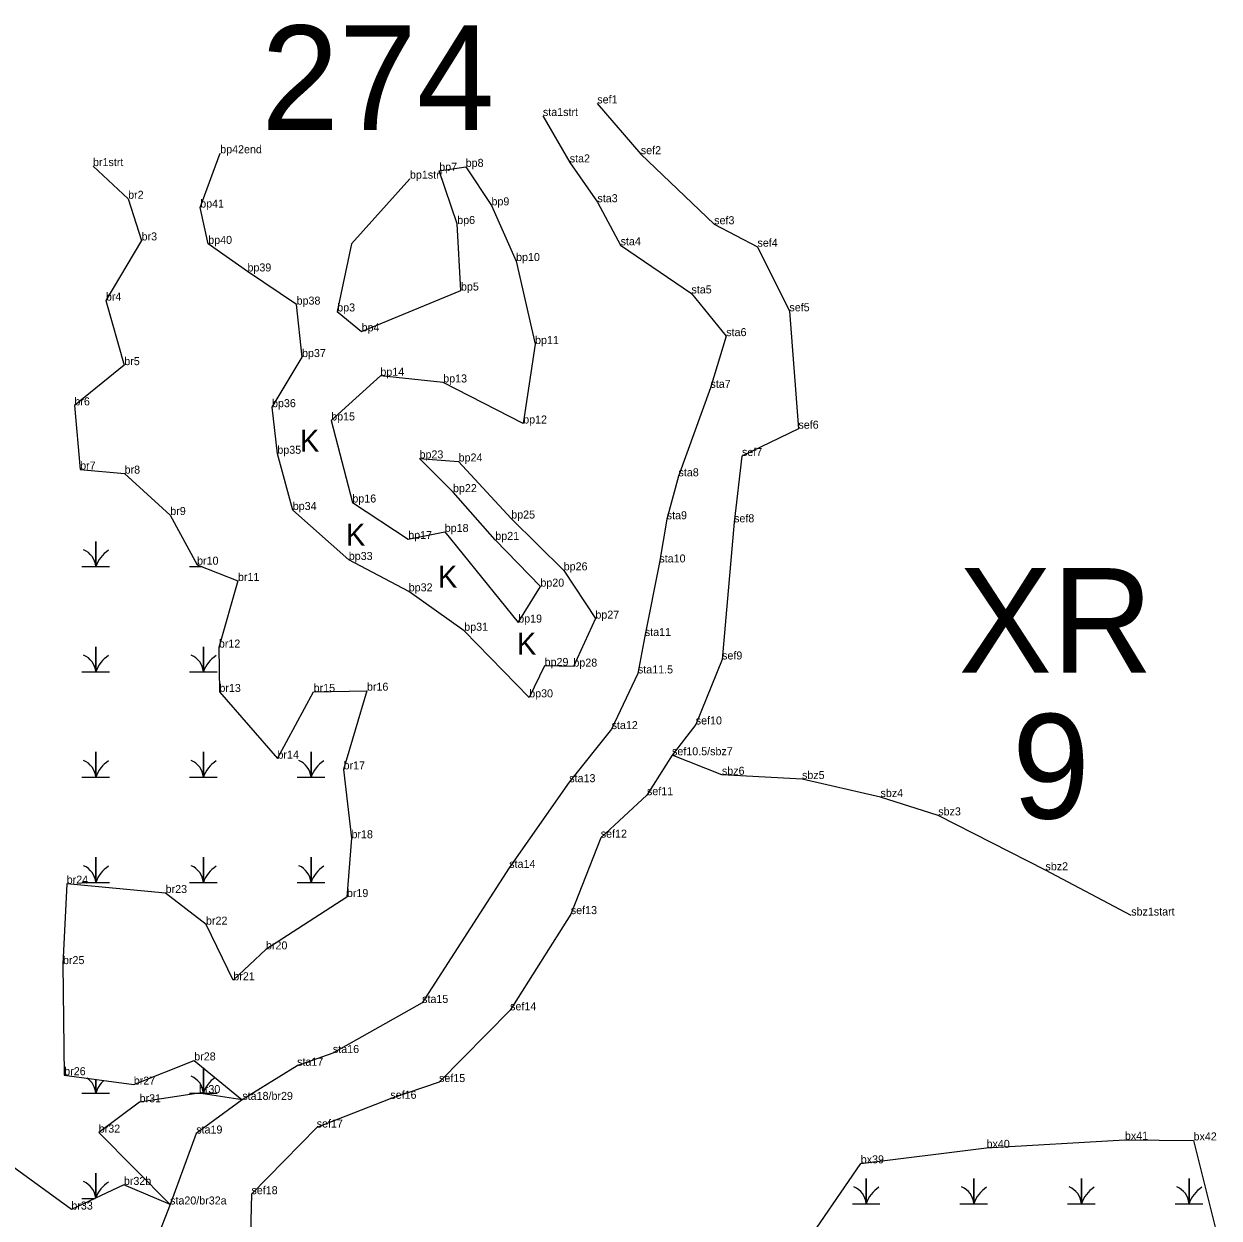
# Model space of a CAD drawing. Extents: x 2072529 to 2268796, y 436423 to 470397.
# Drawn here: x 2233128 to 2233875, y 438303 to 439049 of the extents above; entities that cross this region are included whole.
import ezdxf

# ---------------------------------------------------------------- set-up
doc = ezdxf.new("R2010")
doc.units = 0
for name, color, linetype in [('Default', 7, 'Continuous'), ('Exist Environmental Wetland Boundary', 7, 'Continuous'), ('Exist Environmental Wetland Boundary Cogo Comment', 7, 'Continuous'), ('Exist Environmental Wetland Boundary Cogo Point CELL', 7, 'Continuous'), ('Exist Hydro Jurisdictional Stream or Body of Water NEU Mitigable', 7, 'Continuous'), ('Exist Hydro Jurisdictional Stream or Body of Water NEU Mitigable Cogo Comment', 7, 'Continuous'), ('Exist Hydro Swamp or Marsh', 7, 'Continuous')]:
    doc.layers.add(name, color=color, linetype=linetype)

msp = doc.modelspace()

# ---------------------------------------------------------------- linework, layer by layer
at = {"layer": 'Exist Environmental Wetland Boundary'}
for points in [[(2233369.08, 438952.48), (2233332.65, 438911.67), (2233323.62, 438869.52), (2233338.88, 438857.06), (2233400.97, 438882.57), (2233398.61, 438924.17), (2233387.35, 438957.42), (2233403.91, 438959.87), (2233420.01, 438935.81), (2233435.4, 438901.03), (2233447.25, 438849.14), (2233439.82, 438799.48), (2233389.86, 438825.12), (2233350.61, 438829.32), (2233319.87, 438801.39), (2233333.11, 438750.11), (2233368, 438727.3), (2233390.81, 438731.69), (2233436.71, 438675.09), (2233450.58, 438697.52), (2233422.42, 438726.76), (2233395.99, 438756.59), (2233375.06, 438777.67), (2233399.5, 438775.74), (2233432.37, 438740.1), (2233465.14, 438707.71), (2233484.94, 438677.54), (2233471.2, 438647.57), (2233453.22, 438647.98), (2233443.58, 438628.34), (2233403.01, 438669.96), (2233368.31, 438694.6), (2233330.86, 438714.21), (2233295.86, 438745.43), (2233286.24, 438780.56), (2233282.91, 438809.69), (2233301.66, 438841), (2233298.26, 438873.8), (2233267.57, 438894.51), (2233243.05, 438911.72), (2233238.03, 438934.45), (2233250.54, 438968.37)], [(2233171.06, 438960.35), (2233193.01, 438939.93), (2233201.42, 438913.9), (2233179.1, 438876.33), (2233190.6, 438835.95), (2233159.43, 438810.81), (2233163.02, 438770.7), (2233190.8, 438768.17), (2233219.34, 438742.29), (2233236.09, 438711.26), (2233261.63, 438701.08), (2233249.69, 438659.45), (2233250.03, 438631.71), (2233286.3, 438590.05), (2233308.92, 438631.76), (2233342.21, 438632.51), (2233327.62, 438583.34), (2233332.55, 438540.3), (2233329.68, 438503.54), (2233279.12, 438470.84), (2233258.71, 438451.55), (2233241.66, 438486.32), (2233216.43, 438506.06), (2233154.63, 438511.91), (2233152.31, 438461.64), (2233153.08, 438392.21), (2233196.55, 438386.33), (2233234.31, 438401.46), (2233264.35, 438376.79), (2233237.2, 438381.03), (2233200.17, 438375.31), (2233174.65, 438356.35), (2233219.22, 438311.43), (2233190.35, 438323.66), (2233157.54, 438308.25), (2233110.77, 438342.31)], [(2233613.07, 438282.03), (2233650.73, 438337.13), (2233729.33, 438346.82), (2233815.78, 438351.89), (2233858.66, 438351.45), (2233874.62, 438287.27)]]:
    msp.add_lwpolyline(points, dxfattribs=at)
at = {"layer": 'Exist Environmental Wetland Boundary Cogo Point CELL'}
for p, q in [((2233486.12, 438999.5), (2233486.12, 438999.5)), ((2233452.15, 438991.66), (2233452.15, 438991.66)), ((2233250.54, 438968.37), (2233250.54, 438968.37)), ((2233513.33, 438967.79), (2233513.33, 438967.79)), ((2233171.06, 438960.35), (2233171.06, 438960.35)), ((2233403.91, 438959.87), (2233403.91, 438959.87)), ((2233468.9, 438962.65), (2233468.9, 438962.65)), ((2233387.35, 438957.42), (2233387.35, 438957.42)), ((2233193.01, 438939.93), (2233193.01, 438939.93)), ((2233420.01, 438935.81), (2233420.01, 438935.81)), ((2233486.21, 438937.78), (2233486.21, 438937.78)), ((2233238.03, 438934.45), (2233238.03, 438934.45)), ((2233398.61, 438924.17), (2233398.61, 438924.17)), ((2233559.17, 438924.01), (2233559.17, 438924.01)), ((2233201.42, 438913.9), (2233201.42, 438913.9)), ((2233243.05, 438911.72), (2233243.05, 438911.72)), ((2233500.71, 438910.85), (2233500.71, 438910.85)), ((2233586.22, 438909.97), (2233586.22, 438909.97)), ((2233435.4, 438901.03), (2233435.4, 438901.03)), ((2233267.57, 438894.51), (2233267.57, 438894.51)), ((2233179.1, 438876.33), (2233179.1, 438876.33)), ((2233400.97, 438882.57), (2233400.97, 438882.57)), ((2233544.96, 438880.77), (2233544.96, 438880.77)), ((2233298.26, 438873.8), (2233298.26, 438873.8)), ((2233323.62, 438869.52), (2233323.62, 438869.52)), ((2233606.16, 438869.63), (2233606.16, 438869.63)), ((2233338.88, 438857.06), (2233338.88, 438857.06)), ((2233566.69, 438854.09), (2233566.69, 438854.09)), ((2233447.25, 438849.14), (2233447.25, 438849.14)), ((2233301.66, 438841), (2233301.66, 438841)), ((2233190.6, 438835.95), (2233190.6, 438835.95)), ((2233350.61, 438829.32), (2233350.61, 438829.32)), ((2233389.86, 438825.12), (2233389.86, 438825.12)), ((2233556.83, 438821.76), (2233556.83, 438821.76)), ((2233159.43, 438810.81), (2233159.43, 438810.81)), ((2233282.91, 438809.69), (2233282.91, 438809.69)), ((2233319.87, 438801.39), (2233319.87, 438801.39)), ((2233439.82, 438799.48), (2233439.82, 438799.48)), ((2233611.8, 438796.23), (2233611.8, 438796.23)), ((2233286.24, 438780.56), (2233286.24, 438780.56)), ((2233576.52, 438779.17), (2233576.52, 438779.17)), ((2233375.06, 438777.67), (2233375.06, 438777.67)), ((2233399.5, 438775.74), (2233399.5, 438775.74)), ((2233163.02, 438770.7), (2233163.02, 438770.7)), ((2233190.8, 438768.17), (2233190.8, 438768.17)), ((2233536.87, 438766.48), (2233536.87, 438766.48)), ((2233395.99, 438756.59), (2233395.99, 438756.59)), ((2233333.11, 438750.11), (2233333.11, 438750.11)), ((2233219.34, 438742.29), (2233219.34, 438742.29)), ((2233295.86, 438745.43), (2233295.86, 438745.43)), ((2233432.37, 438740.1), (2233432.37, 438740.1)), ((2233529.52, 438739.65), (2233529.52, 438739.65)), ((2233571.58, 438737.75), (2233571.58, 438737.75)), ((2233368, 438727.3), (2233368, 438727.3)), ((2233390.81, 438731.69), (2233390.81, 438731.69)), ((2233422.42, 438726.76), (2233422.42, 438726.76)), ((2233330.86, 438714.21), (2233330.86, 438714.21)), ((2233524.92, 438712.66), (2233524.92, 438712.66)), ((2233236.09, 438711.26), (2233236.09, 438711.26)), ((2233465.14, 438707.71), (2233465.14, 438707.71)), ((2233261.63, 438701.08), (2233261.63, 438701.08)), ((2233450.58, 438697.52), (2233450.58, 438697.52)), ((2233368.31, 438694.6), (2233368.31, 438694.6)), ((2233436.71, 438675.09), (2233436.71, 438675.09)), ((2233484.94, 438677.54), (2233484.94, 438677.54)), ((2233403.01, 438669.96), (2233403.01, 438669.96)), ((2233249.69, 438659.45), (2233249.69, 438659.45)), ((2233515.84, 438666.68), (2233515.84, 438666.68)), ((2233564.1, 438652.03), (2233564.1, 438652.03)), ((2233453.22, 438647.98), (2233453.22, 438647.98)), ((2233471.2, 438647.57), (2233471.2, 438647.57)), ((2233511.52, 438643.3), (2233511.52, 438643.3)), ((2233250.03, 438631.71), (2233250.03, 438631.71)), ((2233308.92, 438631.76), (2233308.92, 438631.76)), ((2233342.21, 438632.51), (2233342.21, 438632.51)), ((2233443.58, 438628.34), (2233443.58, 438628.34)), ((2233495.08, 438608.51), (2233495.08, 438608.51)), ((2233547.64, 438611.4), (2233547.64, 438611.4)), ((2233286.3, 438590.05), (2233286.3, 438590.05)), ((2233532.82, 438592.15), (2233532.82, 438592.15)), ((2233327.62, 438583.34), (2233327.62, 438583.34)), ((2233564, 438579.97), (2233564, 438579.97)), ((2233614.03, 438577.31), (2233614.03, 438577.31)), ((2233468.61, 438575.33), (2233468.61, 438575.33)), ((2233517.16, 438567.2), (2233517.16, 438567.2)), ((2233663.08, 438566.07), (2233663.08, 438566.07)), ((2233699.15, 438554.56), (2233699.15, 438554.56)), ((2233332.55, 438540.3), (2233332.55, 438540.3)), ((2233488.29, 438540.65), (2233488.29, 438540.65)), ((2233431.11, 438521.76), (2233431.11, 438521.76)), ((2233766.14, 438520.29), (2233766.14, 438520.29)), ((2233154.63, 438511.91), (2233154.63, 438511.91)), ((2233216.43, 438506.06), (2233216.43, 438506.06)), ((2233329.68, 438503.54), (2233329.68, 438503.54)), ((2233469.6, 438492.88), (2233469.6, 438492.88)), ((2233819.71, 438492), (2233819.71, 438492)), ((2233241.66, 438486.32), (2233241.66, 438486.32)), ((2233279.12, 438470.84), (2233279.12, 438470.84)), ((2233152.31, 438461.64), (2233152.31, 438461.64)), ((2233258.71, 438451.55), (2233258.71, 438451.55)), ((2233376.67, 438437.39), (2233376.67, 438437.39)), ((2233431.64, 438432.8), (2233431.64, 438432.8)), ((2233320.95, 438406.06), (2233320.95, 438406.06)), ((2233234.31, 438401.46), (2233234.31, 438401.46)), ((2233298.57, 438398.12), (2233298.57, 438398.12)), ((2233153.08, 438392.21), (2233153.08, 438392.21)), ((2233196.55, 438386.33), (2233196.55, 438386.33)), ((2233387.24, 438387.93), (2233387.24, 438387.93)), ((2233237.2, 438381.03), (2233237.2, 438381.03)), ((2233264.35, 438376.79), (2233264.35, 438376.79)), ((2233264.35, 438376.79), (2233264.35, 438376.79)), ((2233356.82, 438377.47), (2233356.82, 438377.47)), ((2233200.17, 438375.31), (2233200.17, 438375.31)), ((2233174.65, 438356.35), (2233174.65, 438356.35)), ((2233235.56, 438355.78), (2233235.56, 438355.78)), ((2233310.81, 438359.52), (2233310.81, 438359.52)), ((2233729.33, 438346.82), (2233729.33, 438346.82)), ((2233815.78, 438351.89), (2233815.78, 438351.89)), ((2233858.66, 438351.45), (2233858.66, 438351.45)), ((2233650.73, 438337.13), (2233650.73, 438337.13)), ((2233190.35, 438323.66), (2233190.35, 438323.66)), ((2233270.05, 438317.86), (2233270.05, 438317.86)), ((2233219.22, 438311.43), (2233219.22, 438311.43)), ((2233219.22, 438311.43), (2233219.22, 438311.43)), ((2233157.54, 438308.25), (2233157.54, 438308.25))]:
    msp.add_line(p, q, dxfattribs=at)
at = {"layer": 'Exist Hydro Jurisdictional Stream or Body of Water NEU Mitigable'}
for points in [[(2233486.12, 438999.5), (2233513.33, 438967.79), (2233559.17, 438924.01), (2233586.22, 438909.97), (2233606.16, 438869.63), (2233611.8, 438796.23), (2233576.52, 438779.17), (2233571.58, 438737.75), (2233564.1, 438652.03), (2233547.64, 438611.4), (2233532.82, 438592.15), (2233517.16, 438567.2), (2233488.29, 438540.65), (2233469.6, 438492.88), (2233431.64, 438432.8), (2233387.24, 438387.93), (2233356.82, 438377.47), (2233310.81, 438359.52), (2233270.05, 438317.86), (2233268.69, 438260.03)], [(2233452.15, 438991.66), (2233468.9, 438962.65), (2233486.21, 438937.78), (2233500.71, 438910.85), (2233544.96, 438880.77), (2233566.69, 438854.09), (2233556.83, 438821.76), (2233536.87, 438766.48), (2233529.52, 438739.65), (2233524.92, 438712.66), (2233515.84, 438666.68), (2233511.52, 438643.3), (2233495.08, 438608.51), (2233468.61, 438575.33), (2233431.11, 438521.76), (2233376.67, 438437.39), (2233320.95, 438406.06), (2233298.57, 438398.12), (2233264.35, 438376.79), (2233235.56, 438355.78), (2233219.22, 438311.43), (2233210.7, 438289.64)], [(2233819.71, 438492), (2233766.14, 438520.29), (2233699.15, 438554.56), (2233663.08, 438566.07), (2233614.03, 438577.31), (2233564, 438579.97), (2233532.82, 438592.15)]]:
    msp.add_lwpolyline(points, dxfattribs=at)
at = {"layer": 'Exist Hydro Swamp or Marsh'}
for points in [[(2233164.16, 438710.03), (2233172.76, 438710.03), (2233172.76, 438725.81), (2233172.76, 438710.03), (2233181.36, 438710.03)], [(2233231.41, 438710.03), (2233239.16, 438710.03)], [(2233164.16, 438644.23), (2233172.76, 438644.23), (2233172.76, 438660.01), (2233172.76, 438644.23), (2233181.36, 438644.23)], [(2233231.41, 438644.23), (2233240.01, 438644.23), (2233240.01, 438660.01), (2233240.01, 438644.23), (2233248.61, 438644.23)], [(2233164.16, 438578.43), (2233172.76, 438578.43), (2233172.76, 438594.21), (2233172.76, 438578.43), (2233181.36, 438578.43)], [(2233231.41, 438578.43), (2233240.01, 438578.43), (2233240.01, 438594.21), (2233240.01, 438578.43), (2233248.61, 438578.43)], [(2233298.66, 438578.43), (2233307.26, 438578.43), (2233307.26, 438594.21), (2233307.26, 438578.43), (2233315.86, 438578.43)], [(2233164.16, 438512.63), (2233172.76, 438512.63), (2233172.76, 438528.41), (2233172.76, 438512.63), (2233181.36, 438512.63)], [(2233231.41, 438512.63), (2233240.01, 438512.63), (2233240.01, 438528.41), (2233240.01, 438512.63), (2233248.61, 438512.63)], [(2233298.66, 438512.63), (2233307.26, 438512.63), (2233307.26, 438528.41), (2233307.26, 438512.63), (2233315.86, 438512.63)], [(2233231.41, 438381.03), (2233240.01, 438381.03), (2233240.01, 438396.78)], [(2233240.01, 438396.78), (2233240.01, 438381.03), (2233248.61, 438381.03)], [(2233164.16, 438381.03), (2233172.76, 438381.03), (2233172.76, 438389.55)], [(2233172.76, 438389.55), (2233172.76, 438381.03), (2233181.36, 438381.03)], [(2233172.76, 438315.4), (2233172.76, 438331.01), (2233172.76, 438315.4)], [(2233645.48, 438311.93), (2233654.08, 438311.93), (2233654.08, 438327.71), (2233654.08, 438311.93), (2233662.68, 438311.93)], [(2233712.73, 438311.93), (2233721.33, 438311.93), (2233721.33, 438327.71), (2233721.33, 438311.93), (2233729.93, 438311.93)], [(2233779.98, 438311.93), (2233788.58, 438311.93), (2233788.58, 438327.71), (2233788.58, 438311.93), (2233797.18, 438311.93)], [(2233847.23, 438311.93), (2233855.83, 438311.93), (2233855.83, 438327.71), (2233855.83, 438311.93), (2233864.43, 438311.93)], [(2233164.16, 438315.23), (2233172.4, 438315.23)]]:
    msp.add_lwpolyline(points, dxfattribs=at)
for centre, radius, start, end in [((2233160.49, 438709.15), 12.3, 4.14034, 67.53497), ((2233191, 438703.97), 19.22, 122.12745, 161.62219), ((2233160.49, 438643.35), 12.3, 4.14034, 67.53497), ((2233191, 438638.17), 19.22, 122.12745, 161.62219), ((2233227.74, 438643.35), 12.3, 4.14034, 67.53497), ((2233258.25, 438638.17), 19.22, 122.12745, 161.62219), ((2233160.49, 438577.55), 12.3, 4.14034, 67.53497), ((2233191, 438572.37), 19.22, 122.12745, 161.62219), ((2233227.74, 438577.55), 12.3, 4.14034, 67.53497), ((2233258.25, 438572.37), 19.22, 122.12745, 161.62219), ((2233294.99, 438577.55), 12.3, 4.14034, 67.53497), ((2233325.5, 438572.37), 19.22, 122.12745, 161.62219), ((2233160.49, 438511.75), 12.3, 4.14034, 67.53497), ((2233191, 438506.57), 19.22, 122.12745, 161.62219), ((2233227.74, 438511.75), 12.3, 4.14034, 67.53497), ((2233258.25, 438506.57), 19.22, 122.12745, 161.62219), ((2233294.99, 438511.75), 12.3, 4.14034, 67.53497), ((2233325.5, 438506.57), 19.22, 122.12745, 161.62219), ((2233227.74, 438380.15), 12.3, 4.14034, 67.53497), ((2233258.25, 438374.97), 19.22, 124.68213, 161.62219), ((2233160.49, 438380.15), 12.3, 4.14034, 55.31148), ((2233191, 438374.97), 19.22, 133.6793, 161.62219), ((2233160.49, 438314.35), 12.3, 4.88803, 67.53497), ((2233191, 438309.17), 19.22, 122.12745, 161.0015), ((2233641.81, 438311.04), 12.3, 4.14034, 67.53497), ((2233672.32, 438305.87), 19.22, 122.12745, 161.62219), ((2233709.06, 438311.04), 12.3, 4.14034, 67.53497), ((2233739.57, 438305.87), 19.22, 122.12745, 161.62219), ((2233776.31, 438311.04), 12.3, 4.14034, 67.53497), ((2233806.82, 438305.87), 19.22, 122.12745, 161.62219), ((2233843.56, 438311.04), 12.3, 4.14034, 67.53497), ((2233874.07, 438305.87), 19.22, 122.12745, 161.62219)]:
    msp.add_arc(centre, radius, start, end, dxfattribs=at)

# ---------------------------------------------------------------- texts
at = {"layer": 'Default'}
for s, p in [('274', (2233276.11, 438982.9)), ('XR', (2233711.88, 438643.77)), ('9', (2233745.3, 438552.62))]:
    msp.add_text(s, height=65.34, dxfattribs=at).set_placement(p)
at = {"layer": 'Exist Environmental Wetland Boundary Cogo Comment'}
for s, p in [('bp42end', (2233250.54, 438968.37)), ('br1strt', (2233171.06, 438960.35)), ('bp7', (2233387.35, 438957.42)), ('bp8', (2233403.91, 438959.87)), ('bp1strt', (2233369.08, 438952.48)), ('br2', (2233193.01, 438939.93)), ('bp41', (2233238.03, 438934.45)), ('bp9', (2233420.01, 438935.81)), ('bp6', (2233398.61, 438924.17)), ('br3', (2233201.42, 438913.9)), ('bp40', (2233243.05, 438911.72)), ('bp10', (2233435.4, 438901.03)), ('bp39', (2233267.57, 438894.51)), ('bp5', (2233400.97, 438882.57)), ('br4', (2233179.1, 438876.33)), ('bp38', (2233298.26, 438873.8)), ('bp3', (2233323.62, 438869.52)), ('bp4', (2233338.88, 438857.06)), ('bp11', (2233447.25, 438849.14)), ('bp37', (2233301.66, 438841)), ('br5', (2233190.6, 438835.95)), ('bp14', (2233350.61, 438829.32)), ('bp13', (2233389.86, 438825.12)), ('br6', (2233159.43, 438810.81)), ('bp36', (2233282.91, 438809.69)), ('bp15', (2233319.87, 438801.39)), ('bp12', (2233439.82, 438799.48)), ('bp35', (2233286.24, 438780.56)), ('bp23', (2233375.06, 438777.67)), ('bp24', (2233399.5, 438775.74)), ('br7', (2233163.02, 438770.7)), ('br8', (2233190.8, 438768.17)), ('bp22', (2233395.99, 438756.59)), ('bp34', (2233295.86, 438745.43)), ('bp16', (2233333.11, 438750.11)), ('br9', (2233219.34, 438742.29)), ('bp25', (2233432.37, 438740.1)), ('bp18', (2233390.81, 438731.69)), ('bp17', (2233368, 438727.3)), ('bp21', (2233422.42, 438726.76)), ('bp33', (2233330.86, 438714.21)), ('br10', (2233236.09, 438711.26)), ('bp26', (2233465.14, 438707.71)), ('br11', (2233261.63, 438701.08)), ('bp32', (2233368.31, 438694.6)), ('bp20', (2233450.58, 438697.52)), ('bp27', (2233484.94, 438677.54)), ('bp31', (2233403.01, 438669.96)), ('bp19', (2233436.71, 438675.09)), ('br12', (2233249.69, 438659.45)), ('bp29', (2233453.22, 438647.98)), ('bp28', (2233471.2, 438647.57)), ('br15', (2233308.92, 438631.76)), ('br16', (2233342.21, 438632.51)), ('br13', (2233250.03, 438631.71)), ('bp30', (2233443.58, 438628.34)), ('br14', (2233286.3, 438590.05)), ('br17', (2233327.62, 438583.34)), ('br18', (2233332.55, 438540.3)), ('br24', (2233154.63, 438511.91)), ('br23', (2233216.43, 438506.06)), ('br19', (2233329.68, 438503.54)), ('br22', (2233241.66, 438486.32)), ('br20', (2233279.12, 438470.84)), ('br25', (2233152.31, 438461.64)), ('br21', (2233258.71, 438451.55)), ('br28', (2233234.31, 438401.46)), ('br26', (2233153.08, 438392.21)), ('br27', (2233196.55, 438386.33)), ('br30', (2233237.2, 438381.03)), ('br31', (2233200.17, 438375.31)), ('br32', (2233174.65, 438356.35)), ('bx41', (2233815.78, 438351.89)), ('bx42', (2233858.66, 438351.45)), ('bx40', (2233729.33, 438346.82)), ('bx39', (2233650.73, 438337.13)), ('br32b', (2233190.35, 438323.66)), ('br33', (2233157.54, 438308.25))]:
    msp.add_text(s, height=5, dxfattribs=at).set_placement(p)
at = {"layer": 'Exist Hydro Jurisdictional Stream or Body of Water NEU Mitigable Cogo Comment'}
for s, p in [('sef1', (2233486.12, 438999.5)), ('sta1strt', (2233452.15, 438991.66)), ('sef2', (2233513.33, 438967.79)), ('sta2', (2233468.9, 438962.65)), ('sta3', (2233486.21, 438937.78)), ('sef3', (2233559.17, 438924.01)), ('sta4', (2233500.71, 438910.85)), ('sef4', (2233586.22, 438909.97)), ('sta5', (2233544.96, 438880.77)), ('sef5', (2233606.16, 438869.63)), ('sta6', (2233566.69, 438854.09)), ('sta7', (2233556.83, 438821.76)), ('sef6', (2233611.8, 438796.23)), ('sef7', (2233576.52, 438779.17)), ('sta8', (2233536.87, 438766.48)), ('sta9', (2233529.52, 438739.65)), ('sef8', (2233571.58, 438737.75)), ('sta10', (2233524.92, 438712.66)), ('sta11', (2233515.84, 438666.68)), ('sef9', (2233564.1, 438652.03)), ('sta11.5', (2233511.52, 438643.3)), ('sef10', (2233547.64, 438611.4)), ('sta12', (2233495.08, 438608.51)), ('sef10.5/sbz7', (2233532.82, 438592.15)), ('sbz6', (2233564, 438579.97)), ('sta13', (2233468.61, 438575.33)), ('sbz5', (2233614.03, 438577.31)), ('sef11', (2233517.16, 438567.2)), ('sbz4', (2233663.08, 438566.07)), ('sbz3', (2233699.15, 438554.56)), ('sef12', (2233488.29, 438540.65)), ('sta14', (2233431.11, 438521.76)), ('sbz2', (2233766.14, 438520.29)), ('sef13', (2233469.6, 438492.88)), ('sbz1start', (2233819.71, 438492)), ('sta15', (2233376.67, 438437.39)), ('sef14', (2233431.64, 438432.8)), ('sta16', (2233320.95, 438406.06)), ('sta17', (2233298.57, 438398.12)), ('sef15', (2233387.24, 438387.93)), ('sta18/br29', (2233264.35, 438376.79)), ('sef16', (2233356.82, 438377.47)), ('sta19', (2233235.56, 438355.78)), ('sef17', (2233310.81, 438359.52)), ('sta20/br32a', (2233219.22, 438311.43)), ('sef18', (2233270.05, 438317.86))]:
    msp.add_text(s, height=5, dxfattribs=at).set_placement(p)
at = {"layer": 'Exist Hydro Swamp or Marsh'}
for p in [(2233300.26, 438781.95), (2233329, 438723.22), (2233386.48, 438696.98), (2233435.83, 438655.12)]:
    msp.add_text('K', height=13.6, dxfattribs=at).set_placement(p)

doc.saveas('drawing.dxf')
